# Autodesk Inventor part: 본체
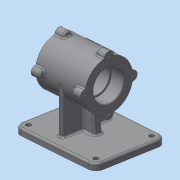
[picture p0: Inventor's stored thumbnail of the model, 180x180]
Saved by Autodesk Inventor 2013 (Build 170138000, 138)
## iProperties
Created: 2015-12
Part Number: 본체
Material: 일반
Document SubType Name: Modeling
Designer: dgall
Density: 1 g/cm^3
Author: dgall
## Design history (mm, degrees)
sketch "스케치1"
  geometry: L1 (0, 0)-(85, 0); L2 (0, 0)-(0, 37); L3 (0, 37)-(85, 37); L4 (85, 37)-(85, 0); L5 (0, 23.5)-(22, 23.5); L6 (22, 23.5)-(22, 21); L7 (22, 21)-(63, 21); L8 (63, 21)-(63, 23.5); L9 (63, 23.5)-(85, 23.5)
  constraints: 18 end point, 4 perpendicular, 2 parallel, 2 point on line, 1 collinear, 1 horizontal
  dimensions: "d0" = 85 distance of L1.start L1.end; "d1" = 47 diameter of L5 L1; "d2" = 47 diameter of L9 L1; "d3" = 42 diameter of L7 L1; "d4" = 74 diameter of L3 L1; "d6" = 22 distance of L5.start L5.end
revolve "회전1" sketch "스케치1" stored, may be unused: angle "d5" = 90 deg
node "작업 평면1"
sketch "스케치2"
  geometry: L1 (-122.5, 55)-(17.5, 55); L2 (17.5, 55)-(17.5, -55); L3 (17.5, -55)-(-122.5, -55); L4 (-122.5, -55)-(-122.5, 55); L5 (-85, 37)-(-85, -37) reference; L6 (0, 37)-(-85, 37) reference; 1 further point
  constraints: 8 end point, 2 parallel, 1 horizontal, 1 perpendicular
  dimensions: "d8" = 140 distance of L1.start L1.end; "d10" = 110 distance of L1.end L2.end; "d11" = 37.5 distance between parallel lines of L5 L4; "d12" = 18 distance between parallel lines of L6 L1
extrude "돌출1" join sketch "스케치2" distance "d13" = 10; taper "d14" = 0 deg
node "작업 평면2"
sketch "스케치3"
  geometry: L1 (55, -80)-(-55, -80) reference; L2 (55, -80)-(55, -70) reference; L3 (-55, -70)-(55, -70) reference; L4 (-55, -80)-(-55, -70) reference; L5 (-37, 0)-(-37, -70); L6 (-55, -70)-(55, -70) reference; L7 (37, 0)-(37, -70); A1 r 37 centre (0, 0) between (-37, 0) and (37, 0) reference; 1 further point
  constraints: 4 end point, 2 point on circle, 2 point on line, 2 tangent, 1 parallel, 1 perpendicular
extrude "돌출2" join sketch "스케치3" stored distance "d15" = 8; taper "d16" = 0 deg
sketch "스케치4"
  geometry: L1 (38.5, 0)-(38.5, 0) reference; L2 (38.5, 0)-(46.5, 0) reference; L3 (46.5, 0)-(46.5, 0) reference; L4 (38.5, 0)-(46.5, 0) reference; L5 (85, -37)-(85, 37) reference; L6 (0, -37)-(0, 37) reference; L7 (122.5, -70)-(-17.5, -70) reference; L8 (-17.5, -70)-(122.5, -70) reference; L9 (122.5, -80)-(-17.5, -80) reference; L10 (122.5, -80)-(122.5, -70) reference; L11 (-17.5, -70)-(122.5, -70) reference; L12 (-17.5, -80)-(-17.5, -70) reference; L13 (0, -37)-(85, -37) reference; L14 (42.5, -37)-(42.5, -70); L15 (38.5, -70)-(46.5, -70) reference; L16 (46.5, -70)-(46.5, 0) reference; L17 (38.5, 0)-(38.5, -70) reference; L18 (0, -37)-(85, -37) reference; L19 (22.839, -26.519)-(17.5, -70); L20 (62.161, -26.519)-(67.5, -70); L21 (22.839, -26.519)-(62.161, -26.519); 1 further point
  constraints: 8 end point, 2 midpoint, 2 point on line, 1 parallel
  dimensions: "d27" = 50 distance of L20.end L19.end; "d29" = 25 distance of L19.end L14.end; "d30" = 97 deg angle of L8 L19; "d31" = 97 deg angle of L7 L20; "d32" = 39.32231 distance of L19.start L20.start
extrude "돌출3" join sketch "스케치4" stored distance "d33" = 12; taper "d34" = 0 deg
fillet "모깎기1" dims "d35" = 12
hole "구멍1" diameter "d38" = 8; stored, may be unused: countersink angle "d42" = 90 deg, drill point angle "d44" = 0 deg; dims "d36" = 10, "d37" = 10, "d39" = 6, "d40" = 4, "d41" = 2, "d43" = 8
sketch "스케치5" dims "d51" = 14
  geometry: C1 r 23.5 at (0, 0) reference; 4 further points
  constraints: 3 vertical alignment, 2 horizontal alignment, 4 other
extrude "돌출4" join sketch "스케치5" distance "d52" = 15; taper "d53" = 0 deg
hole "구멍2" diameter "d56" = 3.459; stored, may be unused: countersink angle "d60" = 90 deg, drill point angle "d62" = 118 deg; dims "d54" = 10, "d55" = 10, "d57" = 9, "d58" = 4, "d59" = 2, "d61" = 11
node "작업 평면3"
fillet "모깎기2" dims "d66" = 3
fillet "모깎기3" dims "d67" = 3
fillet "모깎기4" dims "d68" = 3
fillet "모깎기5" dims "d71" = 3
chamfer "모따기1" distance "d72" = 1; stored, may be unused: second distance "d73" = 2, angle "d74" = 45 deg
fillet "모깎기6" dims "d75" = 0.3
node "작업 평면5"
  node "작업 평면4"
sketch "스케치6"
  geometry: L1 (-42.5, 18.921)-(-42.5, -18.921) reference; L2 (42.5, 18.921)-(42.5, -18.921) reference; 3 further points
  constraints: 1 horizontal alignment, 1 midpoint, 1 other
  dimensions: "d77" = 42.5 distance from line of point (0, 0) L1
feature "엠보싱1" sketch "스케치6" dims "d78" = 0.5, "d79" = 0
node "솔리드1"
pattern_linear "직사각형 패턴1" dims "d47" = 116, "d50" = 86
pattern_circular "원형 패턴1" dims angle "d64" = 360 deg
mirror "대칭1"
node "투영된 루프1"
node "투영된 루프2"
node "투영된 루프3"
other parameters: "d76" = -45 deg
